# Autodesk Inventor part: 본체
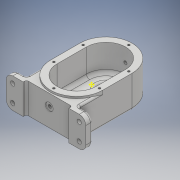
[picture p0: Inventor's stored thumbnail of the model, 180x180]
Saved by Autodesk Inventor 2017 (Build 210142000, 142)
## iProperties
Part Number: 본체
Material: 일반
Document SubType Name: Modeling
Designer: MRC
Density: 1 g/cm^3
Appearance: 기본값
Author: MRC
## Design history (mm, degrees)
sketch "스케치1"
  geometry: L1 (0, -22.5)-(0, 22.5); L2 (40, -22.5)-(40, 22.5); L3 (-40, 22.5)-(-40, -22.5); A1 r 40 centre (0, -22.5) between (-40, -22.5) and (40, -22.5); A2 r 40 centre (0, 22.5) between (40, 22.5) and (-40, 22.5); 1 further point
  constraints: 8 end point, 4 point on circle, 4 tangent, 2 centre point, 1 midpoint, 1 parallel, 1 vertical
  dimensions: "d0" = 80 distance between parallel lines of L2 L3; "d1" = 45 distance of L1.start L1.end
extrude "돌출1" new body sketch "스케치1" stored distance "d2" = 49; taper "d3" = 0 deg
sketch "스케치2"
  geometry: L1 (40, -22.5)-(40, 22.5) reference; L2 (-40, 22.5)-(-40, -22.5) reference; L3 (30, 22.5)-(30, -22.5); L4 (-30, -22.5)-(-30, 22.5); A1 r 40 centre (0, 22.5) between (40, 22.5) and (-40, 22.5) reference; A2 r 40 centre (0, -22.5) between (-40, -22.5) and (40, -22.5) reference; A3 r 30 centre (0, 22.5) between (30, 22.5) and (-30, 22.5); A4 r 30 centre (0, -22.5) between (-30, -22.5) and (30, -22.5)
  constraints: 4 end point, 4 point on circle, 2 centre point, 3 other
  dimensions: "d5" = 10 radial gap between concentric circles of A1 A3
extrude "돌출2" cut sketch "스케치2" distance "d6" = 41; taper "d7" = 0 deg
sketch "스케치5"
  geometry: L1 (0, -22.5)-(0, 22.5); L2 (-26, -22.5)-(-26, 22.5); L3 (26, 22.5)-(26, -22.5); A1 r 26 centre (0, -22.5) between (-26, -22.5) and (26, -22.5); A2 r 26 centre (0, 22.5) between (26, 22.5) and (-26, 22.5); 1 further point
  constraints: 8 end point, 4 point on circle, 4 tangent, 2 centre point, 1 midpoint, 1 parallel, 1 vertical
  dimensions: "d15" = 52 distance between parallel lines of L3 L2; "d16" = 45 distance of L1.start L1.end
extrude "돌출3" join sketch "스케치5" distance "d17" = 11; taper "d18" = 0 deg
sketch "스케치6"
  geometry: L1 (-26, -7.5)-(26, -7.5); L2 (-26, -22.5)-(-26, 22.5) reference; L3 (-26, 22.5)-(-26, -7.5); L4 (26, 22.5)-(26, -22.5) reference; L5 (26, -7.5)-(26, 22.5); A1 r 26 centre (0, 22.5) between (26, 22.5) and (-26, 22.5) reference; A2 r 26 centre (0, 22.5) between (26, 22.5) and (-26, 22.5) reference; A3 r 26 centre (0, 22.5) between (26, 22.5) and (-26, 22.5); 1 further point
  constraints: 6 end point, 2 point on circle, 2 point on line, 1 centre point, 1 coincident, 1 collinear, 1 horizontal
  dimensions: "d19" = 30 distance from line of L1 A1.centre
extrude "돌출4" cut sketch "스케치6" distance "d20" = 3; taper "d21" = 0 deg
hole "구멍2" diameter "d24" = 22; stored, may be unused: countersink angle "d28" = 90 deg, drill point angle "d30" = 0 deg; dims "d25" = 6, "d26" = 28, "d27" = 4, "d29" = 4, "d31" = 10, "d32" = 10
hole "구멍3" diameter "d35" = 28; stored, may be unused: countersink angle "d39" = 90 deg, drill point angle "d41" = 118 deg; dims "d33" = 10, "d34" = 10, "d36" = 6, "d37" = 4, "d38" = 2, "d40" = 8
hole "구멍5" diameter "d53" = 20; stored, may be unused: countersink angle "d57" = 90 deg, drill point angle "d59" = 0 deg; dims "d51" = 10, "d52" = 10, "d54" = 6, "d55" = 28, "d56" = 8, "d58" = 12
node "작업 평면2"
sketch "스케치8"
  geometry: L1 (40, 24.5)-(-40, 24.5) reference; C1 r 6 at (0, 3.5); 1 further point
  constraints: 1 centre point, 1 vertical alignment
  dimensions: "d70" = 12 diameter of C1; "d71" = 21 distance from line of C1.centre L1
extrude "돌출5" join sketch "스케치8" stored distance "d62" = 3; taper "d63" = 0 deg
fillet "모깎기4" dims "d88" = 5
fillet "모깎기5" dims "d89" = 3
sketch "스케치12" dims "d90" = 40
  geometry: C1 r 14 at (0, 22.5) reference; C2 r 11 at (0, 22.5) reference; 3 further points
  constraints: 2 vertical alignment, 1 coincident, 2 other
hole "구멍7" sketch "스케치12" at (0, 42.5) diameter "d91" = 3.242; stored, may be unused: countersink angle "d95" = 90 deg, drill point angle "d97" = 118 deg; dims "d92" = 8, "d93" = 28, "d94" = 8, "d96" = 10
sketch "스케치15"
  geometry: L1 (40, -22.5)-(40, -59.5); L2 (40, -59.5)-(61, -59.5); L3 (61, -59.5)-(61, -69.5); L4 (61, -69.5)-(35, -69.5); L5 (35, -69.5)-(35, -64.5); L6 (35, -64.5)-(-35, -64.5); L7 (-35, -69.5)-(-61, -69.5); L8 (-61, -69.5)-(-61, -59.5); L9 (-61, -59.5)-(-40, -59.5); L10 (-40, 22.5)-(-40, -22.5) reference; L11 (-40, -59.5)-(-40, -22.5); L12 (-35, -64.5)-(-35, -69.5); C1 r 11 at (0, 22.5) reference; A1 r 40 centre (0, -22.5) between (-40, -22.5) and (40, -22.5) reference; A2 r 40 centre (0, -22.5) between (-40, -22.5) and (40, -22.5) reference; 1 further point
  constraints: 22 end point, 3 horizontal, 3 vertical, 2 collinear, 2 perpendicular, 2 tangent, 1 parallel
  dimensions: "d132" = 10 distance of L2.end L3.end; "d133" = 35 distance from line of L5 C1.centre; "d134" = 70 distance of L5.end L6.end; "d135" = 5 distance of L6.end L7.start; "d136" = 92 distance from line of C1.centre L7; "d137" = 122 distance between parallel lines of L3 L8; "d138" = 61 distance from line of C1.centre L8
extrude "돌출9" join sketch "스케치15" distance "d139" = 46; taper "d140" = 0 deg
fillet "모깎기6" dims "d141" = 10
fillet "모깎기7" dims "d142" = 3
fillet "모깎기8" dims "d143" = 3
fillet "모깎기9" dims "d144" = 3
sketch "스케치16"
  geometry: L1 (72, 49)-(-8, 49) reference; 2 further points
  constraints: 1 vertical alignment
  dimensions: "d145" = 21 distance from line of point (32, 28) L1
hole "구멍11" sketch "스케치16" at (32, 28) diameter "d146" = 4.917; stored, may be unused: countersink angle "d150" = 90 deg, drill point angle "d152" = 0 deg; dims "d147" = 135, "d148" = 12, "d149" = 1, "d151" = 17.1
sketch "스케치17"
  geometry: A1 r 7 centre (7, 26) between (7, 33) and (0, 26) reference; A2 r 10 centre (7, 0) between (-3, 0) and (7, -10) reference; A3 r 10 centre (109, 26) between (119, 26) and (109, 36) reference; A4 r 10 centre (109, 0) between (109, -10) and (119, 0) reference; 5 further points
  constraints: 4 coincident
hole "구멍12" sketch "스케치17" at (7, 26), (7, 0), (109, 26), (109, 0) diameter "d153" = 6.6; stored, may be unused: countersink angle "d157" = 90 deg, drill point angle "d159" = 0 deg; dims "d154" = 10, "d155" = 11, "d156" = 2, "d158" = 17.1
sketch "스케치18"
  geometry: L1 (-30, -22.5)-(-30, 22.5) reference; L2 (30, 22.5)-(30, -22.5) reference; L3 (40, -22.5)-(40, 22.5) reference; L4 (-40, 22.5)-(-40, -22.5) reference; L5 (35, 22.5)-(35, -22.5); L6 (-35, -22.5)-(-35, 22.5); A1 r 30 centre (0, 22.5) between (30, 22.5) and (-30, 22.5) reference; A2 r 30 centre (0, -22.5) between (-30, -22.5) and (30, -22.5) reference; A3 r 40 centre (0, 22.5) between (40, 22.5) and (-40, 22.5) reference; A4 r 40 centre (0, -22.5) between (-40, -22.5) and (40, -22.5) reference; A5 r 35 centre (0, 22.5) between (35, 22.5) and (-35, 22.5); A6 r 35 centre (0, -22.5) between (-35, -22.5) and (35, -22.5); 8 further points
  constraints: 7 point on circle, 4 coincident, 4 end point, 2 centre point, 2 horizontal alignment, 3 other
  dimensions: "d160" = 5 radial gap between concentric circles of A3 A5
hole "구멍13" sketch "스케치18" at (-35, 22.5), (-35, -22.5), (0, -57.5), (35, -22.5), (35, 22.5), (0, 57.5) diameter "d161" = 3.242; stored, may be unused: countersink angle "d165" = 90 deg, drill point angle "d167" = 118 deg; dims "d162" = 8, "d163" = 28, "d164" = 8, "d166" = 10
sketch "스케치19"
  geometry: L1 (-51, -69.5)-(-35, -69.5) reference; 2 further points
  constraints: 1 vertical alignment, 1 other
  dimensions: "d168" = 12 distance from line of L1 point (0, -57.5)
feature "엠보싱1" sketch "스케치19" dims "d169" = 0.5, "d170" = 0
fillet "모깎기10" dims "d171" = 0.3
fillet "모깎기11" dims "d172" = 3
fillet "모깎기12" dims "d173" = 3
fillet "모깎기13" dims "d174" = 0.3
node "솔리드1"
pattern_circular "원형 패턴1" dims angle "d99" = 360 deg
node "투영된 루프1"
node "투영된 루프4"
node "투영된 루프7"
